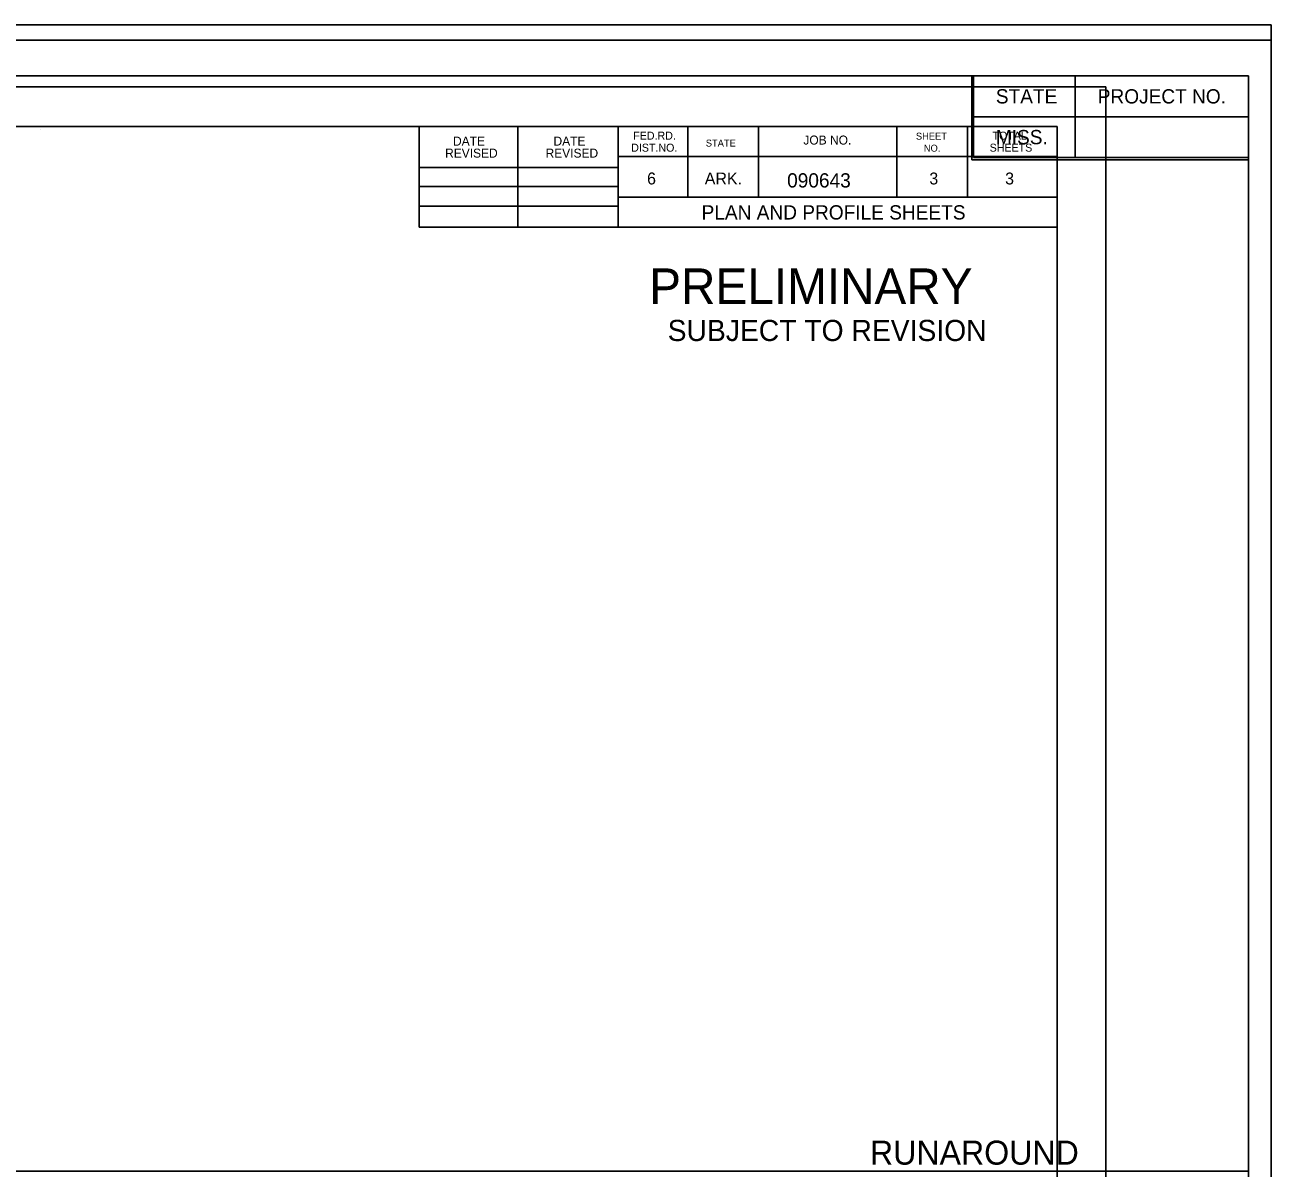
# Model space of a CAD drawing. Extents: x 1384905 to 1388477, y 1972734 to 1975234.
# Drawn here: x 1386053 to 1386665, y 1974486 to 1975047 of the extents above; entities that cross this region are included whole.
import ezdxf

# ---------------------------------------------------------------- set-up
doc = ezdxf.new("R2010")
doc.units = 0
for name, color, linetype in [('R_Border', 7, 'Continuous'), ('R_Border Prem', 7, 'Continuous'), ('R_No Plot', 7, 'Continuous'), ('SHEET_BORDER', 7, 'Continuous'), ('SHEET_BORDER_TX', 7, 'Continuous'), ('SHEET_PLOTTING_SHAPE', 7, 'Continuous')]:
    doc.layers.add(name, color=color, linetype=linetype)

msp = doc.modelspace()

# ---------------------------------------------------------------- linework, layer by layer
at = {"layer": 'R_Border'}
for p, q in [((1384978.84, 1974996.96), (1386559.74, 1974996.96)), ((1386060.97, 1974995.66), (1386060.97, 1974995.66)), ((1386060.97, 1974995.66), (1386060.97, 1974995.66)), ((1386246.54, 1974947.56), (1386246.54, 1974996.96)), ((1386294.94, 1974947.56), (1386294.94, 1974996.96)), ((1386344.24, 1974996.96), (1386344.24, 1974947.56)), ((1386378.44, 1974996.96), (1386378.44, 1974962.26)), ((1386413.14, 1974996.96), (1386413.14, 1974962.26)), ((1386481.04, 1974996.96), (1386481.04, 1974962.26)), ((1386515.74, 1974996.96), (1386515.74, 1974962.26)), ((1386559.74, 1973969.66), (1386559.74, 1974996.96)), ((1386559.74, 1974982.26), (1386344.24, 1974982.26)), ((1386246.54, 1974976.86), (1386344.24, 1974976.86)), ((1386246.54, 1974967.56), (1386344.24, 1974967.56)), ((1386559.74, 1974962.26), (1386344.24, 1974962.26)), ((1386359.04, 1974962.26), (1386559.74, 1974962.26)), ((1386246.54, 1974957.86), (1386344.24, 1974957.86)), ((1386559.74, 1974947.56), (1386246.54, 1974947.56))]:
    msp.add_line(p, q, dxfattribs=at)
at = {"layer": 'R_No Plot'}
msp.add_line((1384916.87, 1975016.45), (1386583.53, 1975016.45), dxfattribs=at)
msp.add_lwpolyline([(1384916.83, 1975016.45), (1386583.53, 1975016.45), (1386583.53, 1973949.76), (1384916.83, 1973949.76)], close=True, dxfattribs=at)
at = {"layer": 'SHEET_BORDER'}
for p, q in [((1386664.63, 1975046.86), (1386664.63, 1975046.86)), ((1384904.64, 1975039.36), (1386664.63, 1975039.36)), ((1384978.64, 1975021.86), (1386653.63, 1975021.86)), ((1386653.63, 1975021.81), (1386653.63, 1973971.86))]:
    msp.add_line(p, q, dxfattribs=at)
msp.add_lwpolyline([(1384978.64, 1975021.86), (1384978.64, 1974484.36), (1386653.63, 1974484.36), (1386653.63, 1974980.66), (1386517.83, 1974980.66), (1386517.83, 1975021.86)], close=True, dxfattribs=at)
at = {"layer": 'SHEET_BORDER_TX'}
for p, q in [((1386518.58, 1975021.81), (1386518.58, 1974981.81)), ((1386568.58, 1975021.81), (1386568.58, 1974981.81)), ((1386653.58, 1975001.81), (1386518.58, 1975001.81)), ((1386518.58, 1974981.81), (1386653.58, 1974981.81))]:
    msp.add_line(p, q, dxfattribs=at)
at = {"layer": 'SHEET_PLOTTING_SHAPE'}
msp.add_lwpolyline([(1384934.64, 1973946.86), (1386664.63, 1973946.86), (1386664.63, 1975046.86), (1384934.64, 1975046.86)], close=True, dxfattribs=at)

# ---------------------------------------------------------------- texts
at = {"layer": 'R_Border'}
for s, height, p in [('FED.RD.', 3.91, (1386351.64, 1974990.56)), ('JOB NO.', 4.396, (1386435.14, 1974988.16)), ('SHEET', 3.42, (1386490.34, 1974990.56)), ('TOTAL', 3.91, (1386527.94, 1974990.56)), ('DATE', 4.396, (1386263.23, 1974987.64)), ('DATE', 4.396, (1386312.53, 1974987.64)), ('DIST.NO.', 3.91, (1386350.64, 1974984.66)), ('STATE', 3.42, (1386387.24, 1974987.16)), ('NO.', 3.42, (1386494.24, 1974984.66)), ('SHEETS', 3.91, (1386526.54, 1974984.66)), ('REVISED', 4.396, (1386259.33, 1974981.74)), ('REVISED', 4.396, (1386308.63, 1974981.74)), ('6', 5.86, (1386358.44, 1974968.56)), ('ARK.', 5.861, (1386386.74, 1974968.56)), ('3', 5.86, (1386496.95, 1974968.56)), ('3', 5.86, (1386534.14, 1974968.56)), ('090643', 7, (1386427.16, 1974967.07)), ('PLAN AND PROFILE SHEETS', 7, (1386385.18, 1974951.37)), ('RUNAROUND', 11.79, (1386467.8, 1974487.55))]:
    msp.add_text(s, height=height, dxfattribs=at).set_placement(p)
at = {"layer": 'R_Border Prem'}
for s, height, p in [('PRELIMINARY', 17.5, (1386359.49, 1974909.87)), ('SUBJECT TO REVISION', 10.3756, (1386368.54, 1974891.73))]:
    msp.add_text(s, height=height, dxfattribs=at).set_placement(p)
at = {"layer": 'SHEET_BORDER_TX'}
for s, height, p in [('STATE', 7, (1386529.58, 1975008.31)), ('PROJECT NO.', 6.9999, (1386579.58, 1975008.31)), ('MISS.', 7, (1386529.58, 1974988.31))]:
    msp.add_text(s, height=height, dxfattribs=at).set_placement(p)

doc.saveas('drawing.dxf')
